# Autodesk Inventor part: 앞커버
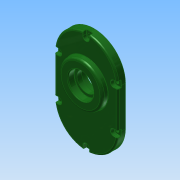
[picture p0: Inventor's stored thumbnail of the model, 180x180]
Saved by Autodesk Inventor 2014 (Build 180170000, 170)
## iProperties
Created: 2016-12
Part Number: 앞커버
Material: 알루미늄 6061
Document SubType Name: Modeling
Designer: mduedu
Density: 2.71 g/cm^3
Appearance: 매끄러움 - 짙은 산림 녹색
Mass: 263.148 g
Surface Area: 259.14 cm^2
Volume: 97.1027 cm^3
Author: mduedu
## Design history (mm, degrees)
sketch "스케치1"
  geometry: L1 (40, -25)-(40, 25); L2 (-40, 25)-(-40, -25); L3 (-40, -25)-(40, 25); L4 (40, -25)-(-40, 25); A1 r 40 centre (0, 25) between (40, 25) and (-40, 25); A2 r 40 centre (0, -25) between (-40, -25) and (40, -25); 1 further point
  constraints: 8 end point, 4 point on circle, 4 tangent, 2 centre point, 2 midpoint, 1 parallel, 1 vertical
  dimensions: "d0" = 130 dimension on A2 A1; "d2" = 80 distance between parallel lines of L1 L2
extrude "돌출1" new body sketch "스케치1" distance "d3" = 10; taper "d4" = 0 deg
sketch "스케치2"
  geometry: C1 r 21 at (0, 11); 1 further point
  constraints: 1 centre point, 1 vertical alignment
  dimensions: "d5" = 42 diameter of C1; "d7" = 11 distance of C1.centre point (0, 0)
extrude "돌출2" join sketch "스케치2" distance "d8" = 7; taper "d9" = 0 deg
sketch "스케치3"
  geometry: C1 r 15 at (0, -33.1); C2 r 21 at (0, 11) reference; 1 further point
  constraints: 1 centre point, 1 vertical alignment
  dimensions: "d10" = 30 diameter of C1; "d71" = 44.1 distance of C1.centre C2.centre
extrude "돌출3" join sketch "스케치3" distance "d12" = 7; taper "d13" = 0 deg
sketch "스케치4"
  geometry: C1 r 28 at (0, 11); A1 r 21 centre (0, 11) between (8.978, -7.984) and (-8.978, -7.984) reference; 1 further point
  constraints: 1 centre point, 1 coincident
  dimensions: "d14" = 56 diameter of C1
extrude "돌출4" join sketch "스케치4" distance "d15" = 7; taper "d16" = -5 deg
hole "구멍1" diameter "d19" = 35; stored, may be unused: countersink angle "d23" = 90 deg, drill point angle "d25" = 0 deg; dims "d17" = 10, "d18" = 10, "d20" = 6, "d21" = 4, "d22" = 2, "d24" = 10
hole "구멍2" diameter "d28" = 22; stored, may be unused: countersink angle "d32" = 90 deg, drill point angle "d34" = 0 deg; dims "d26" = 10, "d27" = 10, "d29" = 6, "d30" = 4, "d31" = 2, "d33" = 7
hole "구멍3" diameter "d37" = 19; stored, may be unused: countersink angle "d41" = 90 deg, drill point angle "d43" = 0 deg; dims "d35" = 10, "d36" = 10, "d38" = 6, "d39" = 4, "d40" = 2, "d42" = 1
hole "구멍4" diameter "d46" = 32; stored, may be unused: countersink angle "d50" = 90 deg, drill point angle "d52" = 0 deg; dims "d44" = 10, "d45" = 10, "d47" = 6, "d48" = 4, "d49" = 2, "d51" = 8
hole "구멍5" diameter "d55" = 25; stored, may be unused: countersink angle "d59" = 90 deg, drill point angle "d61" = 0 deg; dims "d53" = 10, "d54" = 10, "d56" = 6, "d57" = 4, "d58" = 2, "d60" = 8
fillet "모깎기1" dims "d62" = 0.3
fillet "모깎기2" dims "d63" = 2
chamfer "모따기1" distance "d64" = 1; stored, may be unused: second distance "d65" = 2, angle "d66" = 45 deg
fillet "모깎기4" dims "d68" = 2
fillet "모깎기5" dims "d69" = 0.3
fillet "모깎기6" dims "d70" = 2
sketch "스케치5"
  geometry: L1 (-40, 25)-(-40, -25) reference; L2 (40, -25)-(40, 25) reference; L3 (35, 25)-(35, -25); L4 (-35, -25)-(-35, 25); A1 r 40 centre (0, 25) between (40, 25) and (-40, 25) reference; A2 r 40 centre (0, -25) between (-40, -25) and (40, -25) reference; A3 r 35 centre (0, 25) between (35, 25) and (-35, 25); A4 r 35 centre (0, -25) between (-35, -25) and (35, -25); 2 further points
  constraints: 5 point on circle, 4 end point, 2 centre point, 1 vertical alignment, 3 other
  dimensions: "d72" = 5 distance between parallel lines of L2 L3
sketch "스케치7"
  geometry: 1 further point
hole "구멍7" sketch "스케치7" at (0, 60) diameter "d80" = 4.5; stored, may be unused: countersink angle "d84" = 90 deg, drill point angle "d86" = 0 deg; dims "d81" = 6, "d82" = 8, "d83" = 4.6, "d85" = 8
sketch "스케치9"
  geometry: L1 (-4, 0)-(4, 0); L2 (4, 0)-(4, 5); L3 (4, 5)-(-4, 5); L4 (-4, 5)-(-4, 0); C1 r 2.25 at (0, 0) reference; A1 r 40 centre (0, -35) between (40, -35) and (-40, -35) reference; 2 further points
  constraints: 8 end point, 2 parallel, 2 vertical, 1 horizontal, 1 horizontal alignment, 1 perpendicular, 1 tangent, 1 other
extrude "돌출6" cut sketch "스케치9" stored distance "d96" = 3; taper "d97" = 0 deg
fillet "모깎기7" dims "d98" = 0.3
fillet "모깎기8" dims "d99" = 0.3
fillet "모깎기9" dims "d100" = 3
node "솔리드1"
pattern_linear "직사각형 패턴1"
node "투영된 루프1"
